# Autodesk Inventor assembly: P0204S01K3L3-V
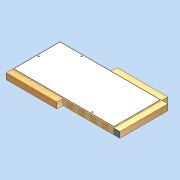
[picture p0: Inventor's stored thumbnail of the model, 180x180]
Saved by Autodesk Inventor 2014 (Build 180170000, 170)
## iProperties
Created: 2011-04
Part Number: P0204S01K3L3-V
Document SubType Name: Assembly
Designer: david.appleford
Mass: 16000 g
Surface Area: 20078.4 cm^2
Volume: 57368 cm^3
Density: 0.278901 g/cm^3
Description: 0.5w x 1w 01 Panel - 3 Locks 3 Lugs
Cost Center: £73.00
Justset: False
Author: david.appleford
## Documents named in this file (4)
- C:\Documents and Settings\john.everitt\Local Settings\My Documents\Vault\Production MkII\VIRTUAL ELEMENTS\Virtual Walls\Virtual Timber + MgO\P0204S01K3L3-V.iam
- C:\Documents and Settings\john.everitt\Local Settings\My Documents\Vault\Production MkII\VIRTUAL ELEMENTS\Virtual Lugs\Superceded Lugs\LA02C3V.ipt
- C:\Documents and Settings\john.everitt\Local Settings\My Documents\Vault\Production MkII\VIRTUAL ELEMENTS\Virtual Lugs\Superceded Lugs\LA02E3V.ipt
- C:\Documents and Settings\john.everitt\Local Settings\My Documents\Vault\Production MkII\Virtual Elements\Virtual Walls\Virtual Timber + MgO\P0204S01K3-V.ipt
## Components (4 placed, 3 different names)
1. P0204S01K3-V:1 — Mate:1, Flush:1, Flush:2, Mate:2, Flush:3, Flush:4, Mate:4, Flush:7, Flush:8
2. LA02E3V:1 — Mate:1, Flush:1, Flush:2
3. LA02C3V:2 — Mate:2, Flush:3, Flush:4
4. LA02C3V:3 — Mate:4, Flush:7, Flush:8
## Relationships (9: Flush 6, Mate 3)
- Mate:1: P0204S01K3-V:1 ↔ LA02E3V:1
- Flush:1: P0204S01K3-V:1 ↔ LA02E3V:1
- Flush:2: P0204S01K3-V:1 ↔ LA02E3V:1
- Mate:2: P0204S01K3-V:1 ↔ LA02C3V:2
- Flush:3: P0204S01K3-V:1 ↔ LA02C3V:2
- Flush:4: P0204S01K3-V:1 ↔ LA02C3V:2
- Mate:4: P0204S01K3-V:1 ↔ LA02C3V:3
- Flush:7: P0204S01K3-V:1 ↔ LA02C3V:3
- Flush:8: P0204S01K3-V:1 ↔ LA02C3V:3
## Named parameters: t = 1 mm, Cl = 2 mm
